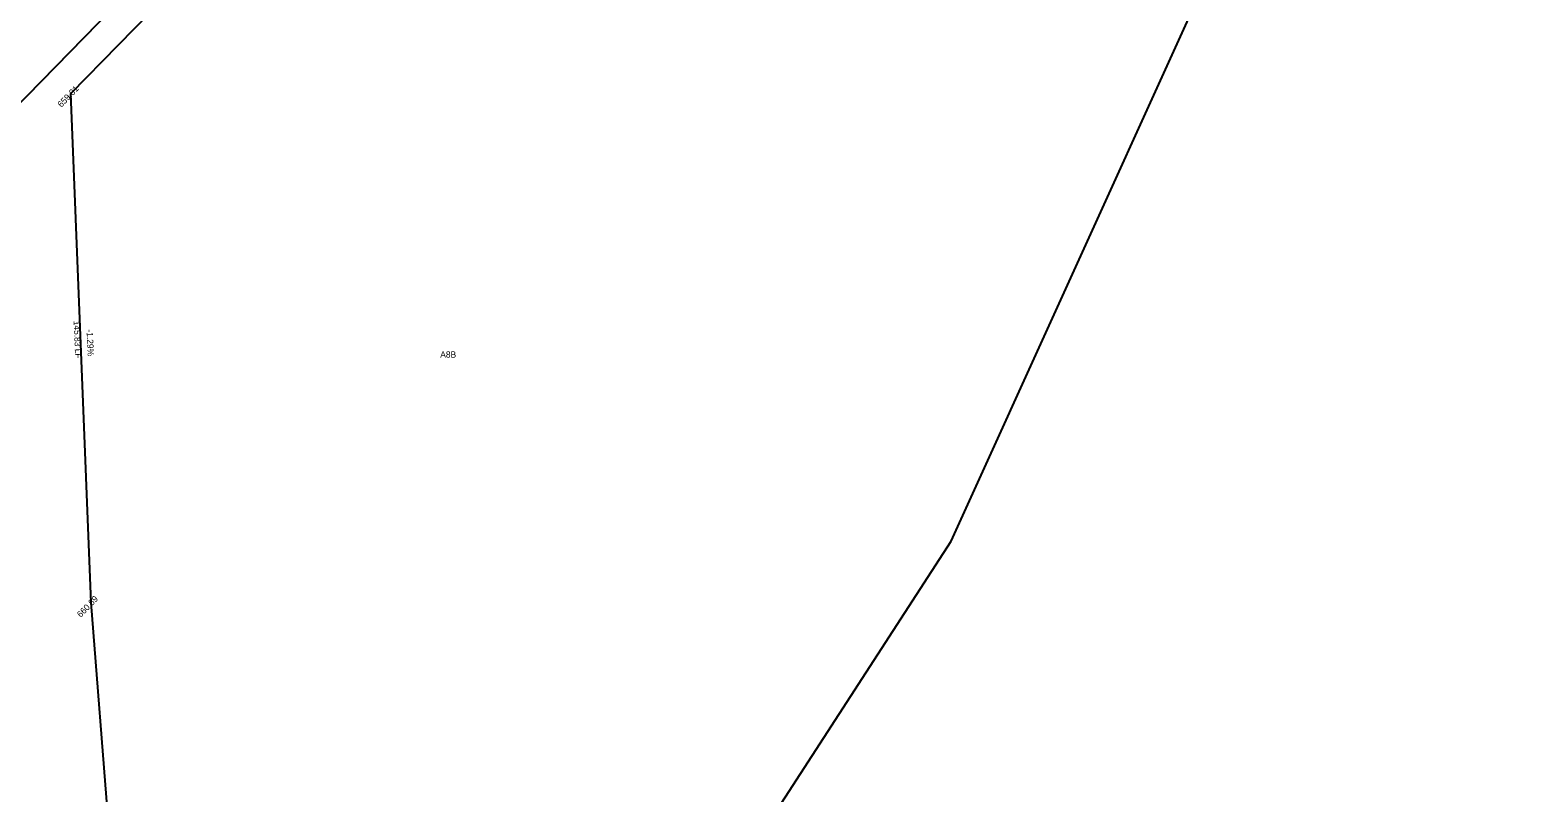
# Model space of a CAD drawing. Extents: x 2252703 to 2264864, y 13787568 to 13790989.
# Drawn here: x 2253731.9 to 2254163.3, y 13789302.7 to 13789520.9 of the extents above; entities that cross this region are included whole.
import ezdxf

# ---------------------------------------------------------------- set-up
doc = ezdxf.new("R2010")
doc.units = 0
for name, color, linetype in [('D_DRAIN_NOTES_1', 7, 'Continuous'), ('D_DRN_AREA_X', 7, 'Continuous'), ('D_DRN_CHANNEL_FLOW', 7, 'Continuous'), ('D_DRN_SHALLOW_CONC_FLOW', 7, 'Continuous'), ('D_DRN_SHEET_FLOW', 7, 'Continuous')]:
    doc.layers.add(name, color=color, linetype=linetype)

msp = doc.modelspace()

# ---------------------------------------------------------------- linework, layer by layer
at = {"layer": 'D_DRN_AREA_X'}
msp.add_line((2253838.31, 13789132.31), (2253995.47, 13789374.64), dxfattribs=at)
for points in [[(2253995.47, 13789374.64), (2254163.3, 13789744.14), (2254077.34, 13789828.32)], [(2253839.66, 13789613.23), (2253833.09, 13789606.51), (2253820.67, 13789593.8), (2253690.3, 13789460.4), (2253689.38, 13789459.45), (2253684.7, 13789454.66), (2253655.27, 13789424.55), (2253614.91, 13789383.25), (2253603.9, 13789371.99)], [(2253603.9, 13789371.99), (2253614.91, 13789383.25), (2253655.27, 13789424.55), (2253684.7, 13789454.66), (2253689.38, 13789459.45), (2253690.3, 13789460.4), (2253820.67, 13789593.8), (2253833.09, 13789606.51), (2253839.66, 13789613.23)]]:
    msp.add_lwpolyline(points, dxfattribs=at)
at = {"layer": 'D_DRN_CHANNEL_FLOW'}
msp.add_line((2253743.62, 13789502.8), (2254037.07, 13789803.07), dxfattribs=at)
msp.add_line((2253743.62, 13789502.8), (2254037.07, 13789803.07), dxfattribs=at)
at = {"layer": 'D_DRN_SHALLOW_CONC_FLOW'}
msp.add_line((2253749.38, 13789357.08), (2253743.62, 13789502.8), dxfattribs=at)
msp.add_line((2253749.38, 13789357.08), (2253743.62, 13789502.8), dxfattribs=at)
at = {"layer": 'D_DRN_SHEET_FLOW'}
msp.add_line((2253772.99, 13789058.01), (2253749.38, 13789357.08), dxfattribs=at)
msp.add_line((2253772.99, 13789058.01), (2253749.38, 13789357.08), dxfattribs=at)

# ---------------------------------------------------------------- texts
at = {"layer": 'D_DRAIN_NOTES_1'}
for s, p in [('659.01', (2253740.88, 13789498.65)), ('660.89', (2253746.43, 13789352.71))]:
    msp.add_text(s, height=1.8, rotation=46.1117, dxfattribs=at).set_placement(p)
msp.add_text('A8B', height=1.8, dxfattribs=at).set_placement((2253849.27, 13789427.18))
at = {"layer": 'D_DRN_SHALLOW_CONC_FLOW'}
for s, p in [('145.83 LF', (2253744.39, 13789437.72)), ('-1.29%', (2253748.09, 13789435.22))]:
    msp.add_text(s, height=1.8, rotation=272.2649, dxfattribs=at).set_placement(p)

doc.saveas('drawing.dxf')
